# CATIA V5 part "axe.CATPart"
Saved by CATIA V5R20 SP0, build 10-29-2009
Part number: 2
Bounding box of the stored display mesh (mm): x -9 to 9, y -9 to 9, z 0 to 500
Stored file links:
  C:\Users\halimelbaba\Documents\cmv\projet\axe.CATPart
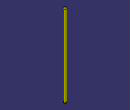
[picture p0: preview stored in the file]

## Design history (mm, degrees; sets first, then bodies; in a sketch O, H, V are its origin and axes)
Body1 (main body)
  Sketch1 on xy-plane, origin (0, 0, 0), H (1, 0, 0), V (0, 1, 0)
    circle A1 centre (0, 0) radius 9
    radius A1 = 9
  Pad1: profile Sketch1, direction (0, 0, 1), length 500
